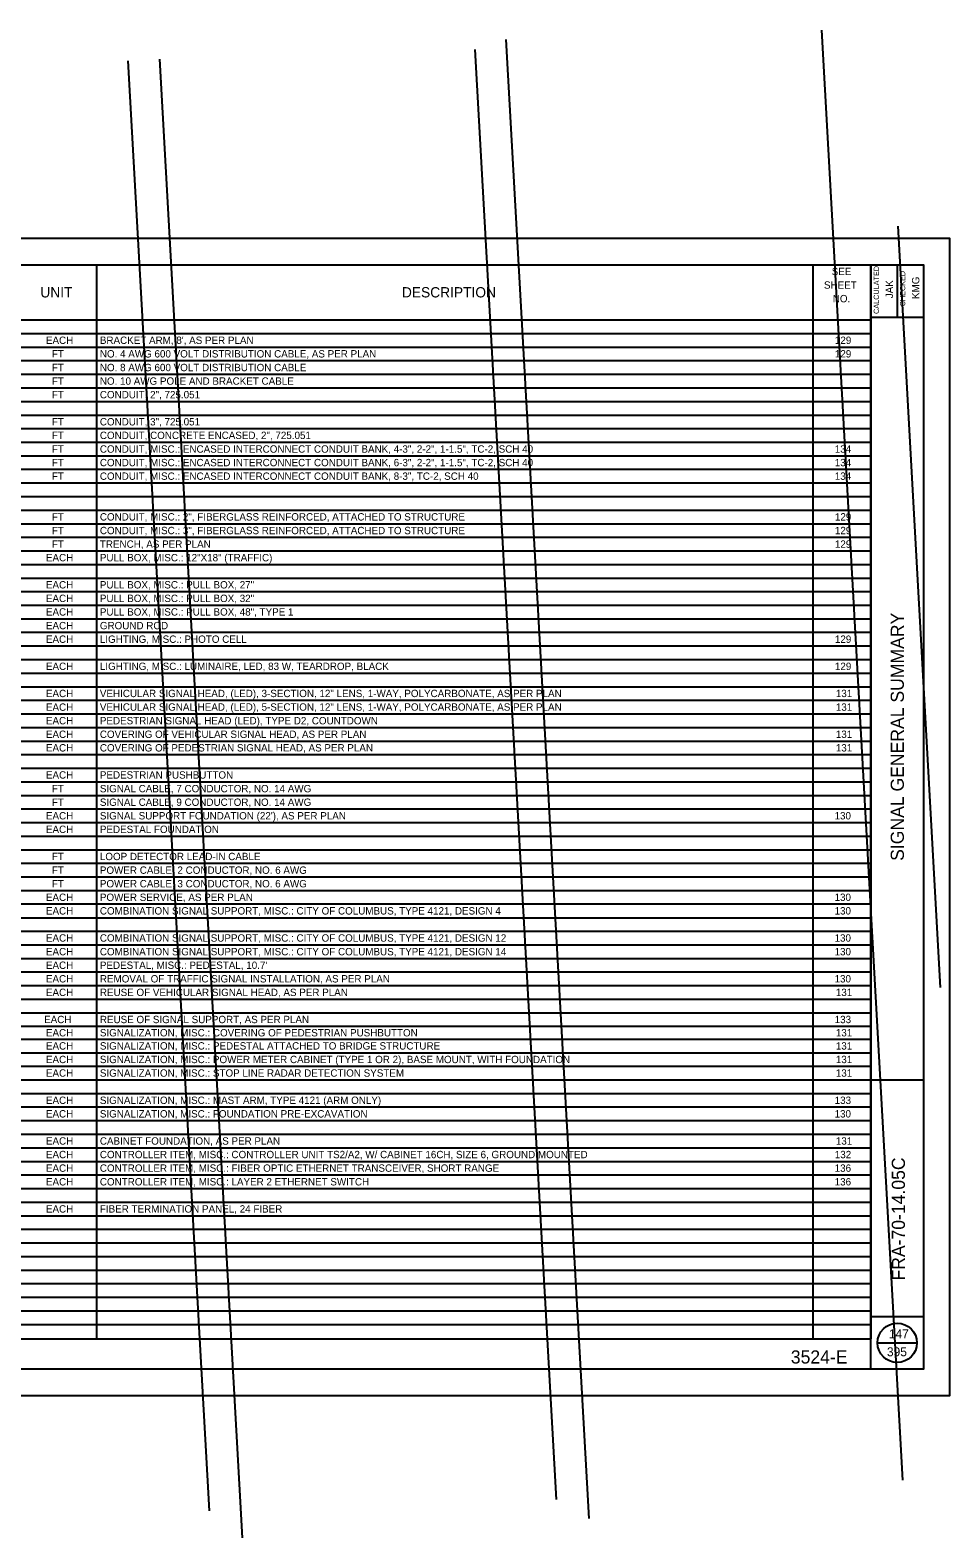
# Model space of a CAD drawing. Extents: x 1822281 to 1823981, y 709999 to 711443.
# Drawn here: x 1823107 to 1823981, y 710010 to 711443 of the extents above; entities that cross this region are included whole.
import ezdxf

# ---------------------------------------------------------------- set-up
doc = ezdxf.new("R2010")
doc.units = 0
for name, color, linetype in [('SC_Scratch1', 7, 'Continuous'), ('SH_Border', 7, 'Continuous'), ('SH_Cut_Line', 7, 'Continuous'), ('SH_Data', 7, 'Continuous'), ('SH_Text', 7, 'Continuous')]:
    doc.layers.add(name, color=color, linetype=linetype)

msp = doc.modelspace()

# ---------------------------------------------------------------- linework, layer by layer
at = {"layer": 'SC_Scratch1'}
for p, q in [((1823859, 711443.4), (1823936.2, 710064.7)), ((1823529.5, 711425), (1823606.7, 710046.3)), ((1823559, 711434.5), (1823637.8, 710028.4)), ((1823199.6, 711414.3), (1823276.8, 710035.6)), ((1823229.5, 711416), (1823308.3, 710009.9)), ((1823931.5, 711257.1), (1823972, 710533.3))]:
    msp.add_line(p, q, dxfattribs=at)
at = {"layer": 'SH_Border'}
for p, q in [((1823906.1, 710170.4), (1823906.1, 711220.4)), ((1823931.1, 711220.4), (1823931.1, 711170.4)), ((1823906.1, 711170.4), (1823956.1, 711170.4)), ((1823906.1, 710445.4), (1823956.1, 710445.4)), ((1823906.1, 710220.4), (1823956.1, 710220.4))]:
    msp.add_line(p, q, dxfattribs=at)
msp.add_lwpolyline([(1822381.1, 711220.4), (1823956.1, 711220.4), (1823956.1, 710170.4), (1822381.1, 710170.4)], close=True, dxfattribs=at)
at = {"layer": 'SH_Cut_Line'}
msp.add_lwpolyline([(1822281.1, 710145.4), (1823981.1, 710145.4), (1823981.1, 711245.4), (1822281.1, 711245.4)], close=True, dxfattribs=at)
at = {"layer": 'SH_Data'}
msp.add_line((1823912.4, 710195.4), (1823949.9, 710195.4), dxfattribs=at)
msp.add_circle((1823931.1, 710195.4), 18.7, dxfattribs=at)
at = {"layer": 'SH_Text'}
for p, q in [((1822381.1, 711220.4), (1823850.7, 711220.4)), ((1823169.8, 711220.4), (1823169.8, 710199.2)), ((1823850.7, 711220.4), (1823906.1, 711220.4)), ((1823850.7, 711220.4), (1823850.7, 710199.2)), ((1823906.1, 711220.4), (1823906.1, 710199.2)), ((1822381.1, 711167.9), (1823906.1, 711167.9)), ((1822381.1, 711155), (1823906.1, 711155)), ((1822381.1, 711142.1), (1823906.1, 711142.1)), ((1822381.1, 711129.2), (1823906.1, 711129.2)), ((1822381.1, 711116.3), (1823906.1, 711116.3)), ((1822381.1, 711103.4), (1823906.1, 711103.4)), ((1822381.1, 711090.4), (1823906.1, 711090.4)), ((1822381.1, 711077.5), (1823906.1, 711077.5)), ((1822381.1, 711064.6), (1823906.1, 711064.6)), ((1822381.1, 711051.7), (1823906.1, 711051.7)), ((1822381.1, 711038.8), (1823906.1, 711038.8)), ((1822381.1, 711025.9), (1823906.1, 711025.9)), ((1822381.1, 711012.9), (1823906.1, 711012.9)), ((1822381.1, 711000), (1823906.1, 711000)), ((1822381.1, 710987.1), (1823906.1, 710987.1)), ((1822381.1, 710974.2), (1823906.1, 710974.2)), ((1822381.1, 710961.3), (1823906.1, 710961.3)), ((1822381.1, 710948.4), (1823906.1, 710948.4)), ((1822381.1, 710935.5), (1823906.1, 710935.5)), ((1822381.1, 710922.5), (1823906.1, 710922.5)), ((1822381.1, 710909.6), (1823906.1, 710909.6)), ((1822381.1, 710896.7), (1823906.1, 710896.7)), ((1822381.1, 710883.8), (1823906.1, 710883.8)), ((1822381.1, 710870.9), (1823906.1, 710870.9)), ((1822381.1, 710858), (1823906.1, 710858)), ((1822381.1, 710845), (1823906.1, 710845)), ((1822381.1, 710832.1), (1823906.1, 710832.1)), ((1822381.1, 710819.2), (1823906.1, 710819.2)), ((1822381.1, 710806.3), (1823906.1, 710806.3)), ((1822381.1, 710793.4), (1823906.1, 710793.4)), ((1822381.1, 710780.5), (1823906.1, 710780.5)), ((1822381.1, 710767.5), (1823906.1, 710767.5)), ((1822381.1, 710754.6), (1823906.1, 710754.6)), ((1822381.1, 710741.7), (1823906.1, 710741.7)), ((1822381.1, 710728.8), (1823906.1, 710728.8)), ((1822381.1, 710715.9), (1823906.1, 710715.9)), ((1822381.1, 710703), (1823906.1, 710703)), ((1822381.1, 710690), (1823906.1, 710690)), ((1822381.1, 710677.1), (1823906.1, 710677.1)), ((1822381.1, 710664.2), (1823906.1, 710664.2)), ((1822381.1, 710651.3), (1823906.1, 710651.3)), ((1822381.1, 710638.4), (1823906.1, 710638.4)), ((1822381.1, 710625.5), (1823906.1, 710625.5)), ((1822381.1, 710612.6), (1823906.1, 710612.6)), ((1822381.1, 710599.6), (1823906.1, 710599.6)), ((1822381.1, 710586.7), (1823906.1, 710586.7)), ((1822381.1, 710573.8), (1823906.1, 710573.8)), ((1822381.1, 710560.9), (1823906.1, 710560.9)), ((1822381.1, 710548), (1823906.1, 710548)), ((1822381.1, 710535.1), (1823906.1, 710535.1)), ((1822381.1, 710522.1), (1823906.1, 710522.1)), ((1822381.1, 710509.2), (1823906.1, 710509.2)), ((1822381.1, 710496.3), (1823906.1, 710496.3)), ((1822381.1, 710484.1), (1823906.1, 710484.1)), ((1822381.1, 710471.2), (1823906.1, 710471.2)), ((1822381.1, 710458.3), (1823906.1, 710458.3)), ((1822381.1, 710445.4), (1823906.1, 710445.4)), ((1822381.1, 710432.5), (1823906.1, 710432.5)), ((1822381.1, 710419.6), (1823906.1, 710419.6)), ((1822381.1, 710406.7), (1823906.1, 710406.7)), ((1822381.1, 710393.7), (1823906.1, 710393.7)), ((1822381.1, 710380.8), (1823906.1, 710380.8)), ((1822381.1, 710367.9), (1823906.1, 710367.9)), ((1822381.1, 710355), (1823906.1, 710355)), ((1822381.1, 710342.1), (1823906.1, 710342.1)), ((1822381.1, 710329.2), (1823906.1, 710329.2)), ((1822381.1, 710316.2), (1823906.1, 710316.2)), ((1822381.1, 710303.3), (1823906.1, 710303.3)), ((1822381.1, 710290.4), (1823906.1, 710290.4)), ((1822381.1, 710277.5), (1823906.1, 710277.5)), ((1822381.1, 710264.6), (1823906.1, 710264.6)), ((1822381.1, 710251.7), (1823906.1, 710251.7)), ((1822381.1, 710238.7), (1823906.1, 710238.7)), ((1822381.1, 710225.8), (1823906.1, 710225.8)), ((1822381.1, 710212.9), (1823906.1, 710212.9)), ((1822381.1, 710199.2), (1823906.1, 710199.2))]:
    msp.add_line(p, q, dxfattribs=at)

# ---------------------------------------------------------------- texts
at = {"layer": 'SH_Data'}
for s, height, p in [('CALCULATED', 5, (1823913.7, 711173.6)), ('CHECKED', 5, (1823938.7, 711180.8)), ('SIGNAL GENERAL SUMMARY', 12.5, (1823937.4, 710653.6))]:
    msp.add_text(s, height=height, rotation=90, dxfattribs=at).set_placement(p)
at = {"layer": 'SH_Text'}
for s, height, p in [('SEE', 6.99, (1823868.8, 711210.5)), ('UNIT', 9.79, (1823116.3, 711189.3)), ('DESCRIPTION', 9.786, (1823460.1, 711189.3)), ('SHEET', 6.99, (1823861.4, 711197.6)), ('NO.', 6.99, (1823869.8, 711184.7)), ('EACH', 6.99, (1823121.6, 711145.1)), ("BRACKET ARM, 8', AS PER PLAN", 6.99, (1823172.9, 711145.1)), ('129', 6.99, (1823871.8, 711145.1)), ('FT', 6.99, (1823127.3, 711132.2)), ('NO. 4 AWG 600 VOLT DISTRIBUTION CABLE, AS PER PLAN', 6.99, (1823172.9, 711132.2)), ('129', 6.99, (1823871.8, 711132.2)), ('FT', 6.99, (1823127.3, 711119.2)), ('NO. 8 AWG 600 VOLT DISTRIBUTION CABLE', 6.99, (1823172.9, 711119.2)), ('FT', 6.99, (1823127.3, 711106.3)), ('NO. 10 AWG POLE AND BRACKET CABLE', 6.99, (1823172.9, 711106.3)), ('FT', 6.99, (1823127.3, 711093.4)), ('CONDUIT, 2", 725.051', 6.99, (1823172.9, 711093.4)), ('FT', 6.99, (1823127.3, 711067.6)), ('CONDUIT, 3", 725.051', 6.99, (1823172.9, 711067.6)), ('FT', 6.99, (1823127.3, 711054.7)), ('FT', 6.99, (1823127.3, 711041.7)), ('CONDUIT, CONCRETE ENCASED, 2", 725.051', 6.99, (1823172.9, 711054.7)), ('CONDUIT, MISC.: ENCASED INTERCONNECT CONDUIT BANK, 4-3", 2-2", 1-1.5", TC-2, SCH 40', 6.99, (1823172.9, 711041.7)), ('134', 6.99, (1823871.7, 711041.7)), ('FT', 6.99, (1823127.3, 711028.8)), ('CONDUIT, MISC.: ENCASED INTERCONNECT CONDUIT BANK, 6-3", 2-2", 1-1.5", TC-2, SCH 40', 6.99, (1823172.9, 711028.8)), ('134', 6.99, (1823871.7, 711028.8)), ('FT', 6.99, (1823127.3, 711015.9)), ('CONDUIT, MISC.: ENCASED INTERCONNECT CONDUIT BANK, 8-3", TC-2, SCH 40', 6.99, (1823172.9, 711015.9)), ('134', 6.99, (1823871.7, 711015.9)), ('FT', 6.99, (1823127.3, 710977.2)), ('CONDUIT, MISC.: 2", FIBERGLASS REINFORCED, ATTACHED TO STRUCTURE', 6.99, (1823172.9, 710977.2)), ('129', 6.99, (1823871.8, 710977.2)), ('FT', 6.99, (1823127.3, 710964.2)), ('CONDUIT, MISC.: 3", FIBERGLASS REINFORCED, ATTACHED TO STRUCTURE', 6.99, (1823172.9, 710964.2)), ('129', 6.99, (1823871.8, 710964.2)), ('FT', 6.99, (1823127.3, 710951.3)), ('TRENCH, AS PER PLAN', 6.99, (1823172.9, 710951.3)), ('129', 6.99, (1823871.8, 710951.3)), ('EACH', 6.99, (1823121.6, 710938.4)), ('PULL BOX, MISC.: 12"X18" (TRAFFIC)', 6.99, (1823172.9, 710938.4)), ('EACH', 6.99, (1823121.6, 710912.6)), ('PULL BOX, MISC.: PULL BOX, 27"', 6.99, (1823172.9, 710912.6)), ('EACH', 6.99, (1823121.6, 710899.7)), ('PULL BOX, MISC.: PULL BOX, 32"', 6.99, (1823172.9, 710899.7)), ('EACH', 6.99, (1823121.6, 710886.8)), ('PULL BOX, MISC.: PULL BOX, 48", TYPE 1', 6.99, (1823172.9, 710886.8)), ('EACH', 6.99, (1823121.6, 710873.8)), ('GROUND ROD', 6.99, (1823172.9, 710873.8)), ('EACH', 6.99, (1823121.6, 710860.9)), ('LIGHTING, MISC.: PHOTO CELL', 6.99, (1823172.9, 710860.9)), ('129', 6.99, (1823871.8, 710860.9)), ('EACH', 6.99, (1823121.6, 710835.1)), ('LIGHTING, MISC.: LUMINAIRE, LED, 83 W, TEARDROP, BLACK', 6.99, (1823172.9, 710835.1)), ('129', 6.99, (1823871.8, 710835.1)), ('EACH', 6.99, (1823121.6, 710809.3)), ('VEHICULAR SIGNAL HEAD, (LED), 3-SECTION, 12" LENS, 1-WAY, POLYCARBONATE, AS PER PLAN', 6.99, (1823172.9, 710809.3)), ('131', 6.99, (1823872.7, 710809.3)), ('EACH', 6.99, (1823121.6, 710796.3)), ('VEHICULAR SIGNAL HEAD, (LED), 5-SECTION, 12" LENS, 1-WAY, POLYCARBONATE, AS PER PLAN', 6.99, (1823172.9, 710796.4)), ('PEDESTRIAN SIGNAL HEAD (LED), TYPE D2, COUNTDOWN', 6.99, (1823172.9, 710783.4)), ('131', 6.99, (1823872.7, 710796.3)), ('EACH', 6.99, (1823121.6, 710783.4)), ('EACH', 6.99, (1823121.6, 710770.5)), ('COVERING OF VEHICULAR SIGNAL HEAD, AS PER PLAN', 6.99, (1823172.9, 710770.5)), ('131', 6.99, (1823872.7, 710770.5)), ('EACH', 6.99, (1823121.6, 710757.6)), ('COVERING OF PEDESTRIAN SIGNAL HEAD, AS PER PLAN', 6.99, (1823172.9, 710757.6)), ('131', 6.99, (1823872.7, 710757.6)), ('EACH', 6.99, (1823121.6, 710731.8)), ('PEDESTRIAN PUSHBUTTON', 6.99, (1823172.9, 710731.8)), ('FT', 6.99, (1823127.3, 710718.8)), ('SIGNAL CABLE, 7 CONDUCTOR, NO. 14 AWG', 6.99, (1823172.9, 710718.8)), ('FT', 6.99, (1823127.3, 710705.9)), ('SIGNAL CABLE, 9 CONDUCTOR, NO. 14 AWG', 6.99, (1823172.9, 710705.9)), ('EACH', 6.99, (1823121.6, 710693)), ("SIGNAL SUPPORT FOUNDATION (22'), AS PER PLAN", 6.99, (1823172.9, 710693)), ('130', 6.99, (1823871.5, 710693)), ('EACH', 6.99, (1823121.6, 710680.1)), ('PEDESTAL FOUNDATION', 6.99, (1823172.9, 710680.1)), ('FT', 6.99, (1823127.3, 710654.3)), ('FT', 6.99, (1823127.3, 710641.3)), ('LOOP DETECTOR LEAD-IN CABLE', 6.99, (1823172.9, 710654.3)), ('POWER CABLE, 2 CONDUCTOR, NO. 6 AWG', 6.99, (1823172.9, 710641.3)), ('FT', 6.99, (1823127.3, 710628.4)), ('POWER CABLE, 3 CONDUCTOR, NO. 6 AWG', 6.99, (1823172.9, 710628.4)), ('EACH', 6.99, (1823121.6, 710615.5)), ('POWER SERVICE, AS PER PLAN', 6.99, (1823172.9, 710615.5)), ('130', 6.99, (1823871.5, 710615.5)), ('EACH', 6.99, (1823121.6, 710602.6)), ('COMBINATION SIGNAL SUPPORT, MISC.: CITY OF COLUMBUS, TYPE 4121, DESIGN 4', 6.99, (1823172.9, 710602.6)), ('130', 6.99, (1823871.5, 710602.6)), ('EACH', 6.99, (1823121.6, 710576.8)), ('COMBINATION SIGNAL SUPPORT, MISC.: CITY OF COLUMBUS, TYPE 4121, DESIGN 12', 6.99, (1823172.9, 710576.8)), ('130', 6.99, (1823871.5, 710576.8)), ('EACH', 6.99, (1823121.6, 710563.8)), ('COMBINATION SIGNAL SUPPORT, MISC.: CITY OF COLUMBUS, TYPE 4121, DESIGN 14', 6.99, (1823172.9, 710563.8)), ('130', 6.99, (1823871.5, 710563.8)), ('EACH', 6.99, (1823121.6, 710550.9)), ("PEDESTAL, MISC.: PEDESTAL, 10.7'", 6.99, (1823172.9, 710550.9)), ('EACH', 6.99, (1823121.6, 710538)), ('REMOVAL OF TRAFFIC SIGNAL INSTALLATION, AS PER PLAN', 6.99, (1823172.9, 710538)), ('130', 6.99, (1823871.5, 710538)), ('EACH', 6.99, (1823121.6, 710525.1)), ('REUSE OF VEHICULAR SIGNAL HEAD, AS PER PLAN', 6.99, (1823172.9, 710525.1)), ('131', 6.99, (1823872.7, 710525.1)), ('EACH ', 6.99, (1823119.9, 710499.3)), ('REUSE OF SIGNAL SUPPORT, AS PER PLAN', 6.99, (1823172.9, 710499.3)), ('133', 6.99, (1823871.6, 710499.3)), ('EACH', 6.99, (1823121.6, 710486.7)), ('SIGNALIZATION, MISC.: COVERING OF PEDESTRIAN PUSHBUTTON', 6.99, (1823172.9, 710486.7)), ('131', 6.99, (1823872.7, 710486.7)), ('EACH', 6.99, (1823121.6, 710474.2)), ('SIGNALIZATION, MISC.: PEDESTAL ATTACHED TO BRIDGE STRUCTURE', 6.99, (1823172.9, 710474.2)), ('131', 6.99, (1823872.7, 710474.2)), ('EACH', 6.99, (1823121.6, 710461.3)), ('SIGNALIZATION, MISC.: POWER METER CABINET (TYPE 1 OR 2), BASE MOUNT, WITH FOUNDATION', 6.99, (1823172.9, 710461.3)), ('131', 6.99, (1823872.7, 710461.3)), ('EACH', 6.99, (1823121.6, 710448.4)), ('SIGNALIZATION, MISC.: STOP LINE RADAR DETECTION SYSTEM', 6.99, (1823172.9, 710448.4)), ('131', 6.99, (1823872.7, 710448.4)), ('EACH', 6.99, (1823121.6, 710422.5)), ('SIGNALIZATION, MISC.: MAST ARM, TYPE 4121 (ARM ONLY)', 6.99, (1823172.9, 710422.5)), ('133', 6.99, (1823871.6, 710422.5)), ('EACH', 6.99, (1823121.6, 710409.6)), ('SIGNALIZATION, MISC.: FOUNDATION PRE-EXCAVATION', 6.99, (1823172.9, 710409.6)), ('130', 6.99, (1823871.5, 710409.6)), ('EACH', 6.99, (1823121.6, 710383.8)), ('CABINET FOUNDATION, AS PER PLAN', 6.99, (1823172.9, 710383.8)), ('131', 6.99, (1823872.7, 710383.8)), ('EACH', 6.99, (1823121.6, 710370.9)), ('CONTROLLER ITEM, MISC.: CONTROLLER UNIT TS2/A2, W/ CABINET 16CH, SIZE 6, GROUND MOUNTED', 6.99, (1823172.9, 710370.9)), ('132', 6.99, (1823871.7, 710370.9)), ('EACH', 6.99, (1823121.6, 710358)), ('CONTROLLER ITEM, MISC.: FIBER OPTIC ETHERNET TRANSCEIVER, SHORT RANGE', 6.99, (1823172.9, 710358)), ('136', 6.99, (1823871.6, 710358)), ('EACH', 6.99, (1823121.6, 710345)), ('CONTROLLER ITEM, MISC.: LAYER 2 ETHERNET SWITCH', 6.99, (1823172.9, 710345)), ('136', 6.99, (1823871.6, 710345)), ('EACH', 6.99, (1823121.6, 710319.2)), ('FIBER TERMINATION PANEL, 24 FIBER', 6.99, (1823172.9, 710319.2)), ('147', 8.5, (1823923.1, 710199.6)), ('395', 8.5, (1823921.3, 710182.6))]:
    msp.add_text(s, height=height, dxfattribs=at).set_placement(p)
for s, height, rotation, p in [('KMG', 7, 90, (1823952.1, 711187.8)), ('JAK', 7, 90, (1823927.1, 711188.5)), ('FRA-70-14.05C', 12.5, 90, (1823938.4, 710254.6)), ('3524-E', 12.5, 359.9999, (1823829.9, 710175.7))]:
    msp.add_text(s, height=height, rotation=rotation, dxfattribs=at).set_placement(p)

doc.saveas('drawing.dxf')
